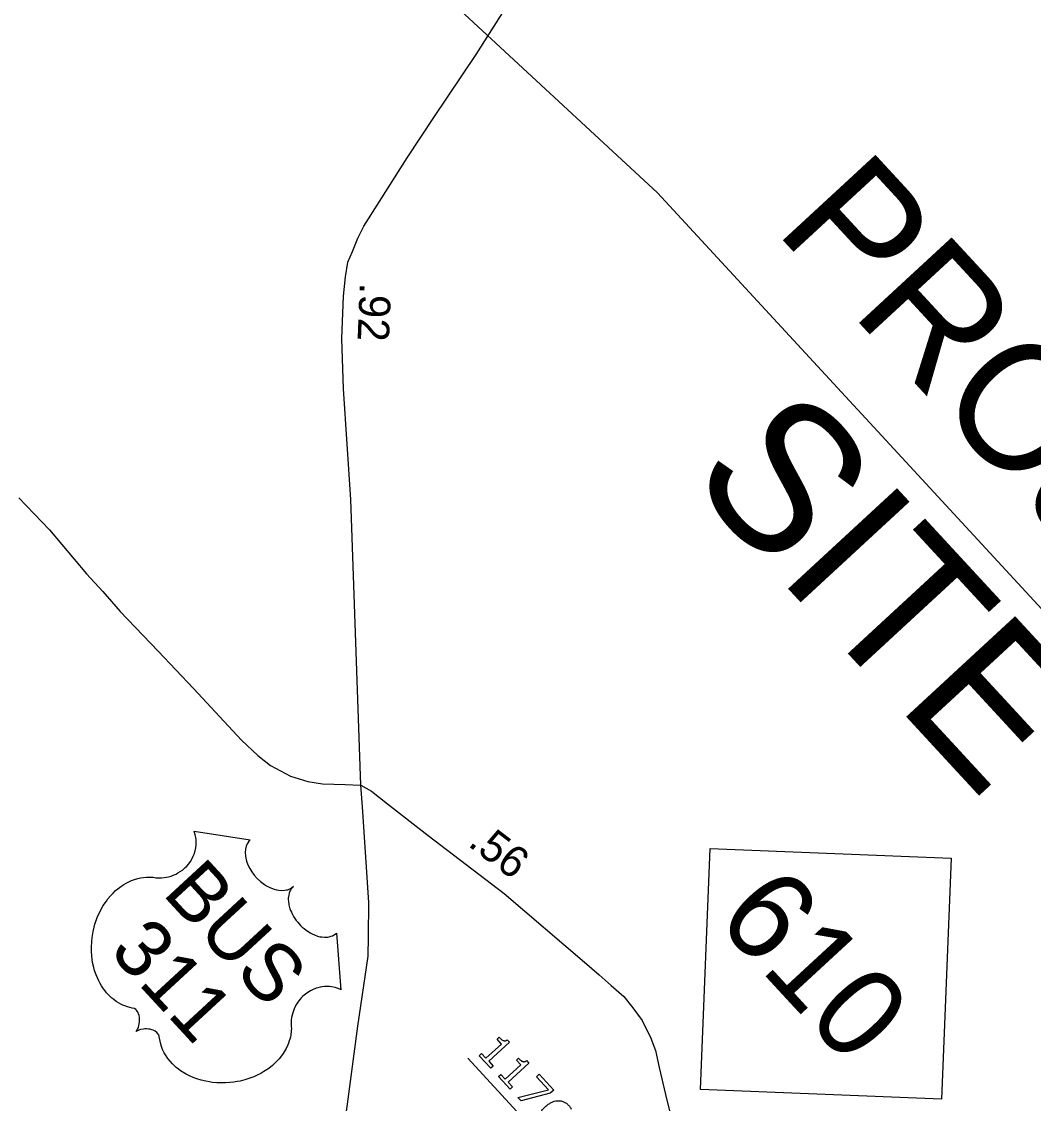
# Model space of a CAD drawing. Extents: x 1695041 to 1706254, y 786537 to 798223.
# Drawn here: x 1703245.1 to 1703431.2, y 796662.3 to 796861.2 of the extents above; entities that cross this region are included whole.
import ezdxf

# ---------------------------------------------------------------- set-up
doc = ezdxf.new("R2010")
doc.units = 0
for name, color, linetype in [('Default', 7, 'Continuous'), ('Old_Level_1', 7, 'Continuous'), ('Old_Level_2', 7, 'Continuous'), ('Old_Level_29', 7, 'Continuous'), ('Old_Level_32', 7, 'Continuous')]:
    doc.layers.add(name, color=color, linetype=linetype)

msp = doc.modelspace()

# ---------------------------------------------------------------- linework, layer by layer
at = {"layer": 'Default'}
msp.add_line((1703327.2, 796670.65), (1703340.99, 796655.72), dxfattribs=at)
for points in [[(1703287.18, 796710.82), (1703286.95, 796710.58), (1703286.71, 796710.25), (1703286.6, 796710.06), (1703286.43, 796709.65), (1703286.3, 796709.11), (1703286.25, 796708.48), (1703286.29, 796707.85), (1703286.36, 796707.46), (1703286.51, 796706.85), (1703286.75, 796706.21), (1703287.08, 796705.55), (1703287.46, 796704.93), (1703287.93, 796704.29), (1703288.44, 796703.71), (1703289.06, 796703.13), (1703289.82, 796702.57), (1703290.19, 796702.33), (1703290.64, 796702.1), (1703291.07, 796701.89), (1703291.59, 796701.71), (1703292.04, 796701.6), (1703292.42, 796701.52), (1703293.01, 796701.48), (1703293.56, 796701.52), (1703293.84, 796701.58), (1703294.1, 796701.64), (1703294.57, 796701.85), (1703294.77, 796701.96), (1703295.12, 796702.24), (1703294.86, 796701.97), (1703294.71, 796701.78), (1703294.59, 796701.57), (1703294.47, 796701.34), (1703294.33, 796700.97), (1703294.25, 796700.63), (1703294.18, 796700.08), (1703294.18, 796699.77), (1703294.2, 796699.5), (1703294.29, 796698.83), (1703294.49, 796698.13), (1703294.6, 796697.8), (1703294.74, 796697.48), (1703294.93, 796697.09), (1703295.15, 796696.71), (1703295.38, 796696.35), (1703295.63, 796695.99), (1703295.91, 796695.64), (1703296.15, 796695.37), (1703296.45, 796695.04), (1703296.75, 796694.76), (1703297.07, 796694.48), (1703297.44, 796694.19), (1703297.75, 796693.98), (1703298.18, 796693.7), (1703298.6, 796693.49), (1703298.99, 796693.31), (1703299.53, 796693.12), (1703299.99, 796692.99), (1703300.37, 796692.94), (1703300.86, 796692.9), (1703301.37, 796692.91), (1703301.72, 796692.96), (1703302.03, 796693.06), (1703302.34, 796693.17), (1703302.64, 796693.34), (1703302.87, 796693.5), (1703303.06, 796693.66), (1703303.82, 796683.24), (1703303.63, 796683.34), (1703303.17, 796683.51), (1703302.78, 796683.63), (1703302.11, 796683.78), (1703301.78, 796683.81), (1703301.45, 796683.83), (1703301.13, 796683.83), (1703300.83, 796683.82), (1703300.42, 796683.77), (1703300.04, 796683.7), (1703299.63, 796683.61), (1703299.3, 796683.51), (1703298.65, 796683.25), (1703298.26, 796683.06), (1703297.95, 796682.87), (1703297.35, 796682.45), (1703297.08, 796682.23), (1703296.82, 796682), (1703296.57, 796681.74), (1703296.34, 796681.48), (1703296.11, 796681.19), (1703295.92, 796680.93), (1703295.7, 796680.59), (1703295.47, 796680.17), (1703295.26, 796679.75), (1703295, 796678.99), (1703294.79, 796678.15), (1703294.72, 796677.62), (1703294.7, 796677.14), (1703294.73, 796676.48), (1703294.74, 796676.11), (1703294.72, 796675.67), (1703294.63, 796674.89), (1703294.56, 796674.55), (1703294.47, 796674.18), (1703294.37, 796673.82), (1703294.24, 796673.44), (1703294.12, 796673.12), (1703293.81, 796672.44), (1703293.45, 796671.82), (1703293.25, 796671.51), (1703292.76, 796670.85), (1703292.51, 796670.54), (1703291.98, 796669.97), (1703291.29, 796669.32), (1703290.58, 796668.77), (1703289.69, 796668.18), (1703289.14, 796667.86), (1703288.46, 796667.52), (1703287.85, 796667.24), (1703286.91, 796666.89), (1703286.19, 796666.67), (1703285.32, 796666.45), (1703284.77, 796666.34), (1703284.16, 796666.25), (1703283.44, 796666.16), (1703282.64, 796666.11), (1703281.74, 796666.1), (1703281.05, 796666.13), (1703280.2, 796666.21), (1703279.71, 796666.28), (1703279.03, 796666.4), (1703278.15, 796666.61), (1703277.33, 796666.87), (1703276.66, 796667.11), (1703276.11, 796667.36), (1703275.41, 796667.7), (1703274.35, 796668.36), (1703273.98, 796668.62), (1703273.57, 796668.96), (1703273.21, 796669.28), (1703272.87, 796669.61), (1703272.43, 796670.08), (1703272.04, 796670.57), (1703271.7, 796671.07), (1703271.37, 796671.62), (1703271.07, 796672.23), (1703270.84, 796672.82), (1703270.65, 796673.46), (1703270.44, 796674.63), (1703270.35, 796674.95), (1703270.27, 796675.1), (1703270.02, 796675.4), (1703269.72, 796675.62), (1703269.35, 796675.79), (1703269.11, 796675.88), (1703268.76, 796675.97), (1703268.47, 796676.01), (1703268.08, 796676.04), (1703267.79, 796676.03), (1703267.56, 796676.02), (1703267.04, 796675.92), (1703266.81, 796675.85), (1703266.54, 796675.75), (1703266.18, 796675.54), (1703266.46, 796675.98), (1703266.61, 796676.32), (1703266.71, 796676.64), (1703266.77, 796676.95), (1703266.82, 796677.38), (1703266.83, 796677.74), (1703266.8, 796678.13), (1703266.73, 796678.51), (1703266.65, 796678.79), (1703266.55, 796679.03), (1703266.4, 796679.3), (1703266.25, 796679.49), (1703266.12, 796679.63), (1703265.89, 796679.79), (1703265.44, 796679.88), (1703265.03, 796679.97), (1703264.59, 796680.09), (1703264.11, 796680.26), (1703263.77, 796680.4), (1703263.39, 796680.59), (1703262.96, 796680.82), (1703262.52, 796681.1), (1703262.1, 796681.42), (1703261.74, 796681.7), (1703261.38, 796682.03), (1703261.07, 796682.34), (1703260.76, 796682.68), (1703260.49, 796683.02), (1703260.19, 796683.41), (1703259.84, 796683.93), (1703259.58, 796684.38), (1703259.31, 796684.88), (1703259.07, 796685.41), (1703258.83, 796686), (1703258.56, 796686.76), (1703258.41, 796687.32), (1703258.2, 796688.24), (1703258.04, 796689.39), (1703257.98, 796690.31), (1703257.97, 796691.03), (1703258.03, 796692.13), (1703258.1, 796692.82), (1703258.29, 796693.97), (1703258.47, 796694.77), (1703258.63, 796695.32), (1703258.92, 796696.17), (1703259.12, 796696.69), (1703259.45, 796697.4), (1703259.77, 796698.03), (1703260.09, 796698.61), (1703260.31, 796698.96), (1703260.72, 796699.55), (1703261.02, 796699.95), (1703261.46, 796700.48), (1703261.96, 796701.01), (1703262.43, 796701.46), (1703262.85, 796701.82), (1703263.36, 796702.21), (1703263.94, 796702.59), (1703264.46, 796702.89), (1703264.85, 796703.09), (1703265.34, 796703.31), (1703265.91, 796703.53), (1703266.49, 796703.69), (1703266.99, 796703.81), (1703267.57, 796703.9), (1703268.09, 796703.94), (1703268.7, 796703.94), (1703269.3, 796703.91), (1703269.81, 796703.83), (1703270.47, 796703.8), (1703270.84, 796703.81), (1703271.33, 796703.86), (1703271.76, 796703.93), (1703272.12, 796704.01), (1703272.64, 796704.15), (1703273.01, 796704.28), (1703273.54, 796704.52), (1703273.89, 796704.71), (1703274.32, 796704.98), (1703274.7, 796705.25), (1703275.15, 796705.63), (1703275.49, 796705.97), (1703275.87, 796706.4), (1703276.19, 796706.84), (1703276.45, 796707.25), (1703276.71, 796707.77), (1703276.88, 796708.18), (1703277.06, 796708.77), (1703277.19, 796709.36), (1703277.24, 796709.9), (1703277.26, 796710.41), (1703277.23, 796710.85), (1703277.18, 796711.25), (1703277.08, 796711.73), (1703276.95, 796712.16), (1703276.86, 796712.41)], [(1703371.75, 796709.22), (1703416.06, 796707.45), (1703414.29, 796663.14), (1703369.98, 796664.91)]]:
    msp.add_lwpolyline(points, close=True, dxfattribs=at)
for points in [[(1703331.41, 796668.81), (1703329.29, 796671.11), (1703329.73, 796671.51), (1703330.54, 796670.63), (1703333.39, 796673.25), (1703332.57, 796674.13), (1703332.96, 796674.49)], [(1703334.46, 796674.05), (1703334.87, 796673.61), (1703331.05, 796670.08), (1703331.85, 796669.21), (1703331.41, 796668.81)], [(1703334.96, 796664.97), (1703332.84, 796667.26), (1703333.28, 796667.66), (1703334.09, 796666.78), (1703336.94, 796669.41), (1703336.12, 796670.29), (1703336.51, 796670.65)], [(1703338.01, 796670.21), (1703338.42, 796669.76), (1703334.6, 796666.23), (1703335.4, 796665.37), (1703334.96, 796664.97)], [(1703342.36, 796664.2), (1703336.98, 796662.79), (1703336.41, 796663.4), (1703342.04, 796664.82), (1703339.81, 796667.23), (1703340.31, 796667.69), (1703342.99, 796664.79), (1703342.36, 796664.2)]]:
    msp.add_lwpolyline(points, dxfattribs=at)
for points in [[(1703332.96, 796674.49), (1703333.12, 796674.31), (1703333.34, 796674.14), (1703333.56, 796673.96), (1703333.72, 796673.91), (1703333.91, 796673.84), (1703334.09, 796673.87), (1703334.27, 796673.89), (1703334.46, 796674.05)], [(1703336.51, 796670.65), (1703336.67, 796670.47), (1703336.89, 796670.29), (1703337.11, 796670.11), (1703337.27, 796670.06), (1703337.46, 796669.99), (1703337.64, 796670.02), (1703337.82, 796670.05), (1703338.01, 796670.21)], [(1703343.72, 796658.24), (1703343.07, 796657.64), (1703342.27, 796657.69), (1703341.47, 796657.74), (1703340.9, 796658.36), (1703340.61, 796658.67), (1703340.47, 796659.02), (1703340.33, 796659.36), (1703340.34, 796659.74), (1703340.35, 796660.2), (1703340.62, 796660.69), (1703340.88, 796661.19), (1703341.43, 796661.69), (1703342, 796662.21), (1703342.55, 796662.5), (1703343.1, 796662.78), (1703343.68, 796662.83), (1703344.23, 796662.87), (1703344.78, 796662.64), (1703345.33, 796662.41), (1703345.81, 796661.89), (1703345.97, 796661.72), (1703346.06, 796661.59), (1703346.15, 796661.46), (1703346.22, 796661.31)]]:
    msp.add_open_spline(points, degree=3, dxfattribs=at)
at = {"layer": 'Old_Level_1'}
for p, q in [((1703210.1, 796970.55), (1703362.1, 796829.74)), ((1703362.1, 796829.74), (1703474.22, 796708.27))]:
    msp.add_line(p, q, dxfattribs=at)
at = {"layer": 'Old_Level_29'}
for points in [[(1703307.5, 796720.88), (1703305.71, 796773.4), (1703304.31, 796793.72), (1703304.04, 796802.98), (1703304.35, 796810.77), (1703304.69, 796814.35), (1703305.1, 796817.04), (1703305.98, 796819), (1703306.98, 796821.46), (1703308.06, 796823.62), (1703310.94, 796828.2), (1703316.06, 796836.2), (1703320.95, 796843.6), (1703328.71, 796855.18), (1703334.05, 796863.57), (1703342.66, 796876.52), (1703344.39, 796879.85), (1703345.42, 796882.91), (1703347.76, 796890.39)], [(1703292.29, 796573.89), (1703294.34, 796588.01), (1703296.84, 796605.59), (1703299.81, 796625.38), (1703300.93, 796634.14), (1703303.19, 796649.26), (1703305.04, 796662.18), (1703306.98, 796676.53), (1703308.84, 796689.44), (1703308.93, 796693.01), (1703308.99, 796699.31), (1703307.85, 796716.87), (1703307.5, 796720.88)], [(1703307.5, 796720.88), (1703309.5, 796719.77), (1703312.4, 796717.43), (1703319.92, 796711.63), (1703333.9, 796700.95), (1703348.65, 796688.34), (1703351.36, 796685.98), (1703353.59, 796684.05), (1703355.88, 796681.99), (1703357.56, 796679.91), (1703359.26, 796677.59), (1703360.86, 796674.32), (1703361.69, 796672.08), (1703362.41, 796668.96), (1703363.53, 796663.99), (1703364.64, 796659.51)]]:
    msp.add_lwpolyline(points, dxfattribs=at)
at = {"layer": 'Old_Level_32'}
msp.add_lwpolyline([(1703244.62, 796773.69), (1703250.25, 796767.82), (1703257.09, 796759.71), (1703260.08, 796756.46), (1703263.23, 796752.81), (1703270.22, 796745.49), (1703276.77, 796738.64), (1703285.56, 796729.11), (1703288.58, 796726.29), (1703290.88, 796724.47), (1703294.58, 796722.49), (1703297.78, 796721.5), (1703300.46, 796721.07), (1703304.66, 796721), (1703307.5, 796720.88)], dxfattribs=at)

# ---------------------------------------------------------------- texts
at = {"layer": 'Default'}
for s, height, rotation, p in [('.92', 5.775, 267.7235, (1703307.34, 796813.28)), ('.56', 5.775, 322.6173, (1703327.02, 796709.84)), ('BUS', 10.569, 312.7091, (1703270.84, 796700.87)), ('610', 16.48, 312.7091, (1703372.51, 796695.94)), ('311', 10.569, 312.7091, (1703261.06, 796690.16))]:
    msp.add_text(s, height=height, rotation=rotation, dxfattribs=at).set_placement(p)
at = {"layer": 'Old_Level_2'}
for s, height, p in [('PROJECT ', 23.173, (1703383.41, 796822.91)), ('SITE', 27.263, (1703367.32, 796777.31))]:
    msp.add_text(s, height=height, rotation=312.7091, dxfattribs=at).set_placement(p)

doc.saveas('drawing.dxf')
